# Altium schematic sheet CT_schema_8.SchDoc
size 405 x 220 mm
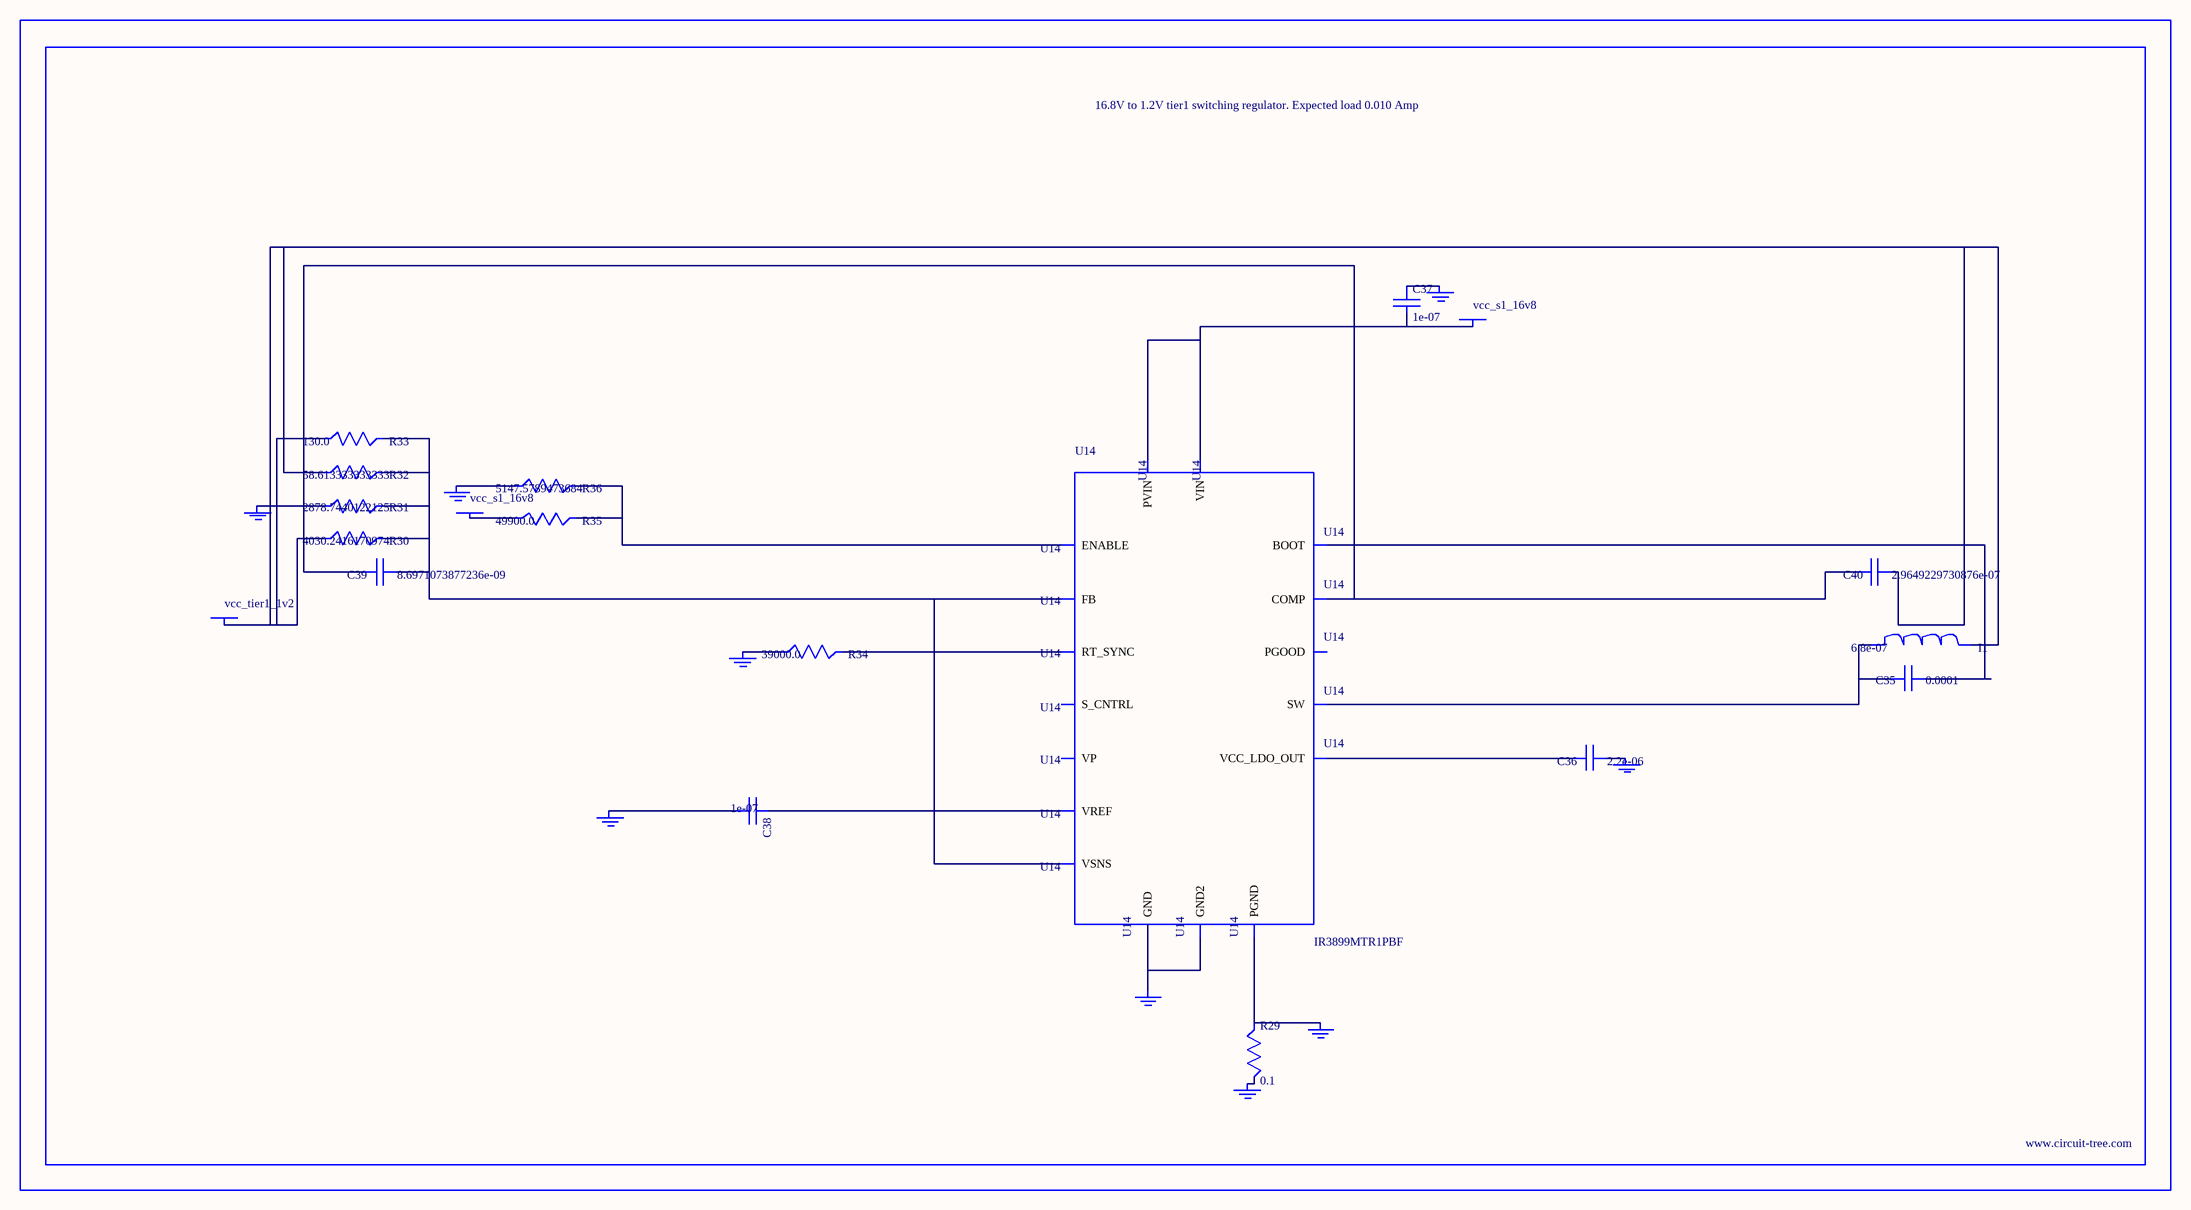
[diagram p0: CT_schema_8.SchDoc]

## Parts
BORDER7  (no value)
C35  0.0001  [C1210]
C36  2.2e-06  [C0603]
C37  1e-07  [C0402]
C38  1e-07  [C0402]
C39  8.6971073877236e-09  [R0603]
C40  2.9649229730876e-07  [R0603]
GND_INSTANCE_7_0  (no value)
GND_INSTANCE_7_1  (no value)
GND_INSTANCE_7_2  (no value)
GND_INSTANCE_7_3  (no value)
GND_INSTANCE_7_4  (no value)
GND_INSTANCE_7_5  (no value)
GND_INSTANCE_7_6  (no value)
GND_INSTANCE_7_7  (no value)
GND_INSTANCE_7_8  (no value)
I1  6.8e-07  [IND25X25CZ]
POWER_INSTANCE_7_0  vcc_s1_16v8
POWER_INSTANCE_7_1  vcc_s1_16v8
POWER_INSTANCE_7_2  vcc_tier1_1v2
R29  0.1  [R0603]
R30  4030.2416170974  [R0603]
R31  2878.7440122125  [R0603]
R32  58.613333333333  [R0603]
R33  130.0  [R0603]
R34  39000.0  [R0603]
R35  49900.0  [R0603]
R36  5147.5789473684  [R0603]
U14  IR3899MTR1PBF  [IR3899MTR1PBF]

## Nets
NetC35_1: C35.1 U14.14(BOOT)
NetC35_2: C35.2 I1.1 U14.12(SW)
NetC36_1: C36.1 GND_INSTANCE_7_4.0(GND)
NetC36_2: C36.2 U14.10(VCC_LDO_OUT)
NetC37_1: C37.1 GND_INSTANCE_7_3.0(GND)
NetC37_2: C37.2 POWER_INSTANCE_7_0.0(PWR) U14.9(VIN) U14.13(PVIN)
NetC38_1: C38.1 U14.2(VREF)
NetC38_2: C38.2 GND_INSTANCE_7_1.0(GND)
NetC39_1: C39.1 R30.2 R31.2 R32.2 R33.2 U14.1(FB) U14.8(VSNS)
NetC39_2: C39.2 C40.2 U14.3(COMP)
NetC40_1: C40.1 I1.2 POWER_INSTANCE_7_2.0(PWR) R30.1 R32.1 R33.1
NetGND_INSTANCE_7_0_0: GND_INSTANCE_7_0.0(GND) R31.1
NetGND_INSTANCE_7_2_0: GND_INSTANCE_7_2.0(GND) R34.1
NetGND_INSTANCE_7_5_0: GND_INSTANCE_7_5.0(GND) R29.2
NetGND_INSTANCE_7_6_0: GND_INSTANCE_7_6.0(GND) R29.1 U14.11(PGND)
NetGND_INSTANCE_7_7_0: GND_INSTANCE_7_7.0(GND) R36.1
NetGND_INSTANCE_7_8_0: GND_INSTANCE_7_8.0(GND) U14.4(GND) U14.17(GND2)
NetPOWER_INSTANCE_7_1_0: POWER_INSTANCE_7_1.0(PWR) R35.1
NetR34_2: R34.2 U14.5(RT_SYNC)
NetR35_2: R35.2 R36.2 U14.15(ENABLE)

Not connected (* = marked no-connect by the designer): U14 6(S_CNTRL) 7(PGOOD) 16(VP)

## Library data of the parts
BORDER7 = BORDER_PAGE7
C35 = GRM32ER61A107ME20L
C36 = C0603C225K8RACTU
C37 C38 = C0402C104K3RACTU
C39 = C39
C40 = C40
GND_INSTANCE_7_0-GND_INSTANCE_7_8 = GND
I1 = IHLP2525CZERR68M01
POWER_INSTANCE_7_0-POWER_INSTANCE_7_2 = PWR
R29 = ERJ-3RSFR10V
R30 = R30
R31 = R31
R32 = R32
R33 = RC0603JR-07130RL
R34 = RC0603JR-0739KL
R35 = RC0603FR-0749K9
R36 = R36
